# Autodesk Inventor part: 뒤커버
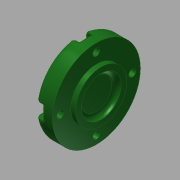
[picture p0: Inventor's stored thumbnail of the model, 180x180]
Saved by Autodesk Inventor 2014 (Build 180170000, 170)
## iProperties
Created: 2015-11
Part Number: 뒤커버
Material: 알루미늄 6061
Document SubType Name: Modeling
Designer: mduedu
Density: 2.71 g/cm^3
Appearance: 매끄러움 - 짙은 산림 녹색
Mass: 68.6419 g
Surface Area: 72.9489 cm^2
Volume: 25.3291 cm^3
Author: mduedu
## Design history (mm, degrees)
sketch "스케치1"
  geometry: L1 (-7, 0)-(7, 0); L2 (-7, 0)-(-7, 27.5); L3 (-7, 27.5)-(4, 27.5); L4 (4, 27.5)-(4, 16); L5 (4, 16)-(7, 16); L6 (7, 16)-(7, 0); 2 further points
  constraints: 12 end point, 3 perpendicular, 2 parallel, 1 coincident, 1 horizontal, 1 midpoint
  dimensions: "d0" = 14 distance of L1.start L1.end; "d1" = 55 diameter of L3 L1; "d2" = 3 distance of L4.end L5.end; "d3" = 32 diameter of L5 L1
revolve "회전1" sketch "스케치1" stored, may be unused: angle "d4" = 90 deg
hole "구멍1" diameter "d7" = 25; stored, may be unused: countersink angle "d11" = 90 deg, drill point angle "d13" = 0 deg; dims "d5" = 10, "d6" = 10, "d8" = 6, "d9" = 4, "d10" = 2, "d12" = 3
fillet "모깎기2" dims "d36" = 3
fillet "모깎기3" dims "d37" = 3
sketch "스케치2" dims "d39" = 45
  geometry: C1 r 12.846 at (0, 0) reference; C2 r 24.5 at (0, 0) reference; 6 further points
  constraints: 2 vertical alignment, 1 coincident, 7 other
  dimensions: "d42" = 360 deg dimension on point (0, 0) point (0, 22.5) (derived)
sketch "스케치3"
  geometry: 8 further points
  constraints: 4 coincident
hole "구멍4" sketch "스케치3" at (-22.5, 0), (0, -22.5), (22.5, 0), (0, 22.5) diameter "d44" = 4.5; stored, may be unused: countersink angle "d48" = 90 deg, drill point angle "d50" = 0 deg; dims "d45" = 6, "d46" = 8, "d47" = 4.6, "d49" = 8
sketch "스케치4"
  geometry: L1 (-4, 0)-(-4, -4.708); L2 (4, 0)-(4, -4.708); A1 r 4 centre (0, 0) between (-4, 0) and (4, 0) reference; A2 r 27.5 centre (0, 22.5) between (-4, -4.708) and (4, -4.708) reference; 3 further points
  constraints: 4 end point, 4 point on circle, 2 tangent, 1 parallel, 1 vertical
extrude "돌출1" cut sketch "스케치4" stored distance "d51" = 0; taper "d52" = 0 deg
fillet "모깎기5" dims "d56" = 0.3
fillet "모깎기6" dims "d57" = 1
node "솔리드1"
pattern_circular "원형 패턴1" dims angle "d54" = 360 deg
